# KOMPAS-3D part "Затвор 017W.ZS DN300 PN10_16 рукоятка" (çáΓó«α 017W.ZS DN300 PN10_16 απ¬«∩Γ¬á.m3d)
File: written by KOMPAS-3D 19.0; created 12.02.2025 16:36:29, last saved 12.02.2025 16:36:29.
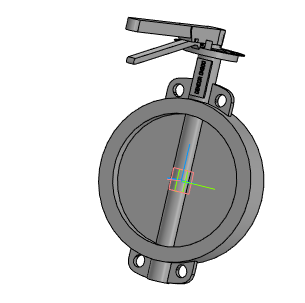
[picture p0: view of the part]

Document properties: Автор: Евгений; Полное имя файла: Затвор 017W.ZS DN300 PN10_16 рукоятка.a3d

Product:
- Part/product: Затвор 017W.ZS DN300 PN10_16 рукоятка
    Масса: 45.4572

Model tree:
1. Операция без истории:1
